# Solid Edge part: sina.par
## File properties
Author: User
Template: iso metric part.par
Last saved by: User
Revision: 1
Application: Solid Edge
Accuracy: 0.990
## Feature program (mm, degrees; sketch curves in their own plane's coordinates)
sketch for "unnamed Protrusion 1" plane through (0, 0, 0) normal (0, -1, 0) x-axis (1, 0, 0)
  line (-21, -15) -> (21, -15)
  line (21, -15) -> (21, 15)
  line (21, 15) -> (-21, 15)
  line (-21, 15) -> (-21, -15)
  dimension (linear) = 21
  dimension (linear) = 21
extrude "unnamed Protrusion 1" add finite 120 symmetric
sketch for "unnamed Cutout 1" plane through (0, -60, 0) normal (0, -1, 0) x-axis (1, 0, 0)
  line (-5, 25) -> (5, 25)
  line (5, 25) -> (5, 5)
  line (5, 5) -> (-5, 5)
  line (-5, 5) -> (-5, 25)
  dimension (linear) = 5
extrude "unnamed Cutout 1" cut through along -normal
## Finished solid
Body 1: solid body, 10 faces, 24 edges, 16 vertices.
  Faces by surface: plane 10
  Edges by curve: line 24
Bounding box of the edges (mm): 42.000 x 120.000 x 30.000, from (-21, -60, -15) to (21, 60, 15).
Planar faces by outward normal: +x 2, +y 1, +z 3, -x 2, -y 1, -z 1
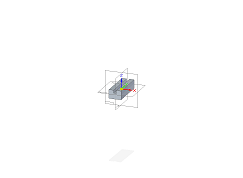
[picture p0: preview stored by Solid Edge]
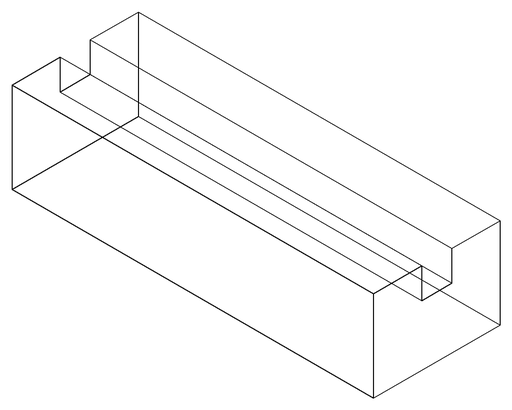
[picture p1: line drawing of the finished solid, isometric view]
